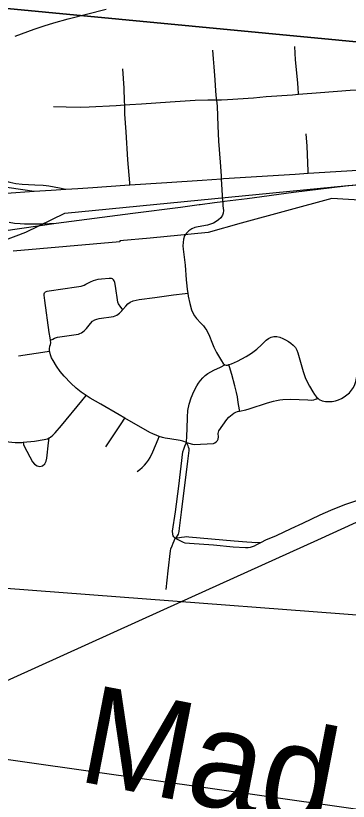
# Model space of a CAD drawing. Extents: x 0 to 34, y 0 to 22.
# Drawn here: x 6.536 to 6.857, y 19.001 to 19.759 of the extents above; entities that cross this region are included whole.
import ezdxf

# ---------------------------------------------------------------- set-up
doc = ezdxf.new("R2010")
doc.units = 0
for name, color, linetype in [('GM_X_City_Street', 7, 'Continuous'), ('GM_X_Corporation', 7, 'Continuous'), ('GM_X_Major_River_Text', 7, 'Continuous'), ('GM_X_Rail_Line', 7, 'Continuous'), ('GM_X_State_Route', 7, 'Continuous'), ('GM_X_Township_Road', 7, 'Continuous'), ('GM_X_US_Route', 7, 'Continuous'), ('SH_Text', 7, 'Continuous')]:
    doc.layers.add(name, color=color, linetype=linetype)

msp = doc.modelspace()

# ---------------------------------------------------------------- linework, layer by layer
at = {"layer": 'GM_X_City_Street'}
for points in [[(6.73606, 19.57997), (6.73629, 19.57584), (6.73663, 19.57115), (6.73642, 19.56869), (6.73581, 19.56661), (6.73418, 19.56425), (6.73206, 19.56219), (6.72964, 19.56044), (6.72706, 19.55899), (6.72429, 19.55791), (6.72138, 19.55714), (6.7122, 19.5555), (6.7091, 19.55468), (6.70611, 19.55343), (6.70338, 19.55166), (6.70105, 19.54935), (6.69928, 19.54657), (6.69817, 19.54348), (6.6977, 19.54026), (6.69769, 19.53705), (6.69791, 19.5339), (6.69967, 19.51846), (6.70082, 19.50417), (6.7013, 19.49845), (6.70171, 19.49486), (6.70224, 19.49145)], [(6.5649, 19.49253), (6.56657, 19.49312), (6.56867, 19.49364), (6.5949, 19.4973), (6.59944, 19.4981), (6.60225, 19.49902), (6.60408, 19.49994), (6.60833, 19.50234), (6.61131, 19.50367), (6.61349, 19.50424), (6.61596, 19.5047), (6.61889, 19.50516), (6.62634, 19.50596), (6.62824, 19.5059), (6.62931, 19.50551)], [(6.63974, 19.47561), (6.63908, 19.4763), (6.63776, 19.47768), (6.63546, 19.48089), (6.63484, 19.48273), (6.63248, 19.49804), (6.63185, 19.50172), (6.63128, 19.50332), (6.6307, 19.5043), (6.62931, 19.50551)], [(6.56982, 19.44585), (6.56961, 19.44807), (6.56846, 19.45347), (6.56427, 19.48416), (6.56364, 19.48927), (6.56375, 19.49081), (6.56416, 19.49168), (6.5649, 19.49253)], [(6.63974, 19.47561), (6.64252, 19.47889), (6.64457, 19.48103), (6.64686, 19.48273), (6.64947, 19.48382), (6.65236, 19.48453), (6.65535, 19.48506), (6.67053, 19.48716), (6.68859, 19.48967), (6.69989, 19.49113), (6.70224, 19.49145)], [(6.70224, 19.49145), (6.70271, 19.48849), (6.70436, 19.48147), (6.70596, 19.47538), (6.70713, 19.47238), (6.70869, 19.46957), (6.71059, 19.46698), (6.71488, 19.46241), (6.71734, 19.45976), (6.71889, 19.45783), (6.7206, 19.45517), (6.72317, 19.44991), (6.72538, 19.44408), (6.72756, 19.43904), (6.73013, 19.43401), (6.73481, 19.42587), (6.73654, 19.42349), (6.73792, 19.42213)], [(6.56982, 19.44585), (6.57201, 19.44699), (6.57368, 19.44784), (6.57643, 19.44876), (6.59674, 19.45175), (6.59823, 19.45221), (6.59972, 19.45303), (6.60242, 19.45493), (6.60453, 19.45733), (6.6083, 19.46215), (6.6104, 19.46413), (6.61275, 19.4657), (6.61441, 19.46625), (6.61676, 19.46672), (6.63062, 19.46876), (6.63237, 19.4693), (6.63374, 19.46995), (6.6363, 19.47195), (6.63852, 19.47419), (6.63974, 19.47561)], [(6.82773, 19.38979), (6.82907, 19.38868), (6.83213, 19.38737), (6.83532, 19.38679), (6.83848, 19.38659), (6.84166, 19.38676), (6.84475, 19.38732), (6.84779, 19.38819), (6.85068, 19.38945), (6.85336, 19.39108), (6.85589, 19.39299), (6.85827, 19.39511), (6.86042, 19.39751), (6.86221, 19.40018), (6.86356, 19.40309), (6.8645, 19.40614), (6.86573, 19.41233), (6.86641, 19.41854), (6.86707, 19.4278), (6.86786, 19.43703), (6.86906, 19.44935), (6.87038, 19.46171), (6.87067, 19.46703)], [(6.74207, 19.42227), (6.74453, 19.42314), (6.75026, 19.42567), (6.75855, 19.43006), (6.76385, 19.43343), (6.76882, 19.43726), (6.77357, 19.44137), (6.7779, 19.44577), (6.78023, 19.44761), (6.78277, 19.44897), (6.78551, 19.44959), (6.78834, 19.44945), (6.79122, 19.4487), (6.79402, 19.44756), (6.79674, 19.44622), (6.79937, 19.44468), (6.80187, 19.44294), (6.80418, 19.44105), (6.80614, 19.43889), (6.80761, 19.43642), (6.80865, 19.43365), (6.81096, 19.42464), (6.81354, 19.41567), (6.81562, 19.40975), (6.81689, 19.40685), (6.81984, 19.40138), (6.82294, 19.39599), (6.82458, 19.39334), (6.82652, 19.39079), (6.82773, 19.38979)], [(6.569, 19.43526), (6.56879, 19.43749), (6.56934, 19.44006), (6.56989, 19.44188), (6.57006, 19.44343), (6.56982, 19.44585)], [(6.5388, 19.43081), (6.56645, 19.43488), (6.569, 19.43526)], [(6.6043, 19.3925), (6.59938, 19.39575), (6.59456, 19.39959), (6.5893, 19.40429), (6.5829, 19.41103), (6.57901, 19.41582), (6.57546, 19.4209), (6.57228, 19.42615), (6.57095, 19.42889), (6.56985, 19.43173), (6.56906, 19.43462), (6.569, 19.43526)], [(6.70098, 19.34699), (6.7015, 19.35347), (6.70167, 19.36018), (6.70194, 19.3716), (6.70252, 19.37793), (6.70372, 19.3842), (6.70556, 19.39031), (6.70803, 19.39618), (6.71106, 19.4018), (6.7128, 19.40448), (6.71473, 19.40704), (6.71684, 19.40947), (6.71918, 19.41171), (6.72172, 19.41371), (6.72446, 19.41543), (6.72731, 19.41689), (6.73382, 19.41986), (6.73792, 19.42213)], [(6.73792, 19.42213), (6.7392, 19.4218), (6.74061, 19.42177), (6.74207, 19.42227)], [(6.7523, 19.37737), (6.75212, 19.37854), (6.75101, 19.38587), (6.75021, 19.39113), (6.74949, 19.39539), (6.74786, 19.40188), (6.74475, 19.41272), (6.74268, 19.42011), (6.74207, 19.42227)], [(6.56842, 19.35155), (6.56969, 19.35221), (6.57223, 19.35425), (6.5744, 19.35656), (6.58045, 19.36363), (6.60015, 19.38748), (6.6043, 19.3925)], [(6.64165, 19.37051), (6.63597, 19.37375), (6.61854, 19.38399), (6.60815, 19.38996), (6.6043, 19.3925)], [(6.7523, 19.37737), (6.75823, 19.37864), (6.76166, 19.37954), (6.77919, 19.38528), (6.7851, 19.38705), (6.78809, 19.38779), (6.79112, 19.38829), (6.79417, 19.3886), (6.80153, 19.38883), (6.81833, 19.38824), (6.82207, 19.38807), (6.82386, 19.38839), (6.82568, 19.38884), (6.82684, 19.38938), (6.82773, 19.38979)], [(6.70098, 19.34699), (6.70672, 19.34538), (6.70833, 19.34515), (6.72709, 19.34607), (6.72836, 19.34667), (6.7298, 19.34772), (6.73089, 19.34886), (6.73169, 19.3504), (6.73189, 19.35269), (6.73174, 19.35567), (6.73184, 19.35721), (6.73244, 19.35845), (6.74009, 19.36939), (6.74178, 19.37148), (6.74342, 19.37297), (6.74501, 19.37416), (6.7467, 19.37531), (6.74854, 19.37626), (6.75033, 19.37695), (6.7523, 19.37737)], [(6.62316, 19.34283), (6.63801, 19.36505), (6.64165, 19.37051)], [(6.67482, 19.35294), (6.67241, 19.3537), (6.66854, 19.35537), (6.66579, 19.35677), (6.64165, 19.37051)], [(6.51602, 19.35276), (6.51749, 19.35181), (6.52034, 19.35036), (6.52331, 19.34921), (6.52636, 19.34833), (6.52946, 19.3477), (6.5326, 19.34731), (6.53574, 19.34711), (6.54203, 19.34723), (6.54343, 19.34737)], [(6.54343, 19.34737), (6.54376, 19.34523), (6.54433, 19.3434), (6.55259, 19.32834), (6.55446, 19.32601), (6.5568, 19.32445), (6.55951, 19.32396), (6.56217, 19.32466), (6.56429, 19.3264), (6.5656, 19.32891), (6.56627, 19.33187), (6.56804, 19.34668), (6.56842, 19.35155)], [(6.54343, 19.34737), (6.55438, 19.34849), (6.56364, 19.34986), (6.56677, 19.35072), (6.56842, 19.35155)], [(6.65348, 19.31914), (6.65593, 19.32102), (6.65826, 19.32304), (6.66045, 19.32524), (6.66246, 19.32759), (6.66426, 19.33009), (6.66589, 19.3327), (6.66862, 19.3382), (6.67375, 19.35039), (6.67482, 19.35294)], [(6.70098, 19.34699), (6.69766, 19.34825), (6.69496, 19.34893), (6.68486, 19.35049), (6.68039, 19.35135), (6.67786, 19.35198), (6.67482, 19.35294)], [(6.69008, 19.25467), (6.68875, 19.25596), (6.68813, 19.25708), (6.68773, 19.25864), (6.6877, 19.26138), (6.69039, 19.28003), (6.69366, 19.30495), (6.69766, 19.33798), (6.69835, 19.34079), (6.69943, 19.34366), (6.70098, 19.34699)], [(6.69008, 19.25467), (6.69157, 19.25577), (6.69249, 19.25697), (6.69329, 19.25846), (6.69404, 19.26122), (6.69448, 19.26425), (6.69629, 19.2797), (6.70247, 19.32909), (6.70373, 19.33941), (6.70368, 19.34096), (6.70316, 19.34263), (6.70259, 19.34394), (6.70098, 19.34699)], [(6.77337, 19.25081), (6.77776, 19.25296), (6.78797, 19.25735), (6.80216, 19.26385), (6.81336, 19.26931), (6.83021, 19.27731), (6.84035, 19.2817), (6.84753, 19.2847), (6.85493, 19.28754), (6.86825, 19.29215)], [(6.68136, 19.20493), (6.68346, 19.22327), (6.68555, 19.2424), (6.68607, 19.24435), (6.68721, 19.24727), (6.68836, 19.24974), (6.68922, 19.25204), (6.69008, 19.25467)], [(6.69008, 19.25467), (6.69622, 19.25577), (6.69915, 19.25611), (6.70093, 19.25623), (6.70345, 19.25611), (6.74722, 19.25195), (6.75939, 19.25104), (6.76403, 19.25067), (6.7676, 19.25057), (6.77337, 19.25081)], [(6.69008, 19.25467), (6.69513, 19.25198), (6.69771, 19.25078), (6.69938, 19.25032), (6.70396, 19.24986), (6.72714, 19.24825), (6.74624, 19.24639), (6.75807, 19.24557), (6.76045, 19.24561), (6.76269, 19.24595), (6.76484, 19.24657), (6.76679, 19.24733), (6.76903, 19.24852), (6.77337, 19.25081)]]:
    msp.add_lwpolyline(points, dxfattribs=at)
at = {"layer": 'GM_X_Corporation'}
for points in [[(6.08229, 20.82057), (7.08216, 20.72429), (6.98964, 19.72208), (5.99165, 19.81795)], [(5.99165, 19.81795), (6.98964, 19.72208), (6.90013, 18.71944), (5.88574, 18.80005)]]:
    msp.add_lwpolyline(points, close=True, dxfattribs=at)
msp.add_lwpolyline([(6.87344, 19.58087), (6.84126, 19.58277), (6.75382, 19.55888), (6.72199, 19.54982), (6.66595, 19.54451), (6.6367, 19.54173), (6.63668, 19.54101), (6.53366, 19.53196)], dxfattribs=at)
at = {"layer": 'GM_X_Rail_Line'}
for points in [[(6.53564, 19.73954), (6.55422, 19.74644), (6.56362, 19.74961), (6.57295, 19.75257), (6.58675, 19.75632), (6.62343, 19.76579)], [(6.49404, 19.53075), (6.54586, 19.55038), (6.58368, 19.56862), (6.85677, 19.5953), (7.4786, 19.63746), (7.52247, 19.64761), (7.56455, 19.65381), (7.67346, 19.65135), (7.70398, 19.6675), (7.78072, 19.69476), (7.84922, 19.71332), (7.8975, 19.72324), (7.94081, 19.72696), (7.9728, 19.72642), (8.01023, 19.72509), (8.06456, 19.71873), (8.1184, 19.70918), (8.15442, 19.70042), (8.43186, 19.60569), (8.84939, 19.56695)], [(6.3823, 19.05105), (6.67911, 19.18588), (6.82772, 19.25299), (7.02632, 19.34372), (7.34943, 19.49118), (7.47336, 19.54747)]]:
    msp.add_lwpolyline(points, dxfattribs=at)
at = {"layer": 'GM_X_State_Route'}
msp.add_line((6.7132, 19.57686), (6.71419, 19.57699), dxfattribs=at)
for points in [[(6.73606, 19.57997), (6.73769, 19.58018), (6.75961, 19.58291), (6.8044, 19.58886), (6.8545, 19.595), (6.87992, 19.59746), (6.8869, 19.59796)], [(6.52738, 19.58798), (6.5542, 19.5897)], [(6.71419, 19.57699), (6.72805, 19.57881), (6.73606, 19.57997)], [(6.57539, 19.55886), (6.64915, 19.56856), (6.69536, 19.57451), (6.7132, 19.57686)], [(6.47278, 19.54455), (6.52439, 19.55146), (6.57539, 19.55886)]]:
    msp.add_lwpolyline(points, dxfattribs=at)
at = {"layer": 'GM_X_Township_Road'}
for points in [[(6.73043, 19.67765), (6.73009, 19.6796), (6.72971, 19.68264), (6.72943, 19.68669), (6.72885, 19.69745), (6.72778, 19.70981), (6.72726, 19.71777), (6.72663, 19.72609)], [(6.80905, 19.68313), (6.80901, 19.68451), (6.80884, 19.68896), (6.80851, 19.69457), (6.80636, 19.71684), (6.80586, 19.72314), (6.80551, 19.72947)], [(6.64142, 19.67288), (6.64131, 19.67678), (6.6408, 19.68928), (6.63977, 19.70795)], [(6.88463, 19.68815), (6.88123, 19.68815), (6.87636, 19.68815), (6.85898, 19.68697), (6.83045, 19.68472), (6.80905, 19.68313)], [(6.73043, 19.67765), (6.7216, 19.67766), (6.70955, 19.67739), (6.68545, 19.67595), (6.65773, 19.67405), (6.64647, 19.67321), (6.64142, 19.67288)], [(6.80905, 19.68313), (6.80348, 19.68272), (6.77811, 19.68084), (6.76577, 19.6798), (6.74058, 19.67792), (6.7349, 19.6777), (6.73043, 19.67765)], [(6.73486, 19.60184), (6.7347, 19.60474), (6.73373, 19.61771), (6.73243, 19.63814), (6.73157, 19.65311), (6.73091, 19.67203), (6.73075, 19.67479), (6.73043, 19.67765)], [(6.64142, 19.67288), (6.63318, 19.67236), (6.60701, 19.67093), (6.59867, 19.67077), (6.58492, 19.671), (6.57258, 19.67124)], [(6.64639, 19.59598), (6.64624, 19.59792), (6.6446, 19.62026), (6.6427, 19.64721), (6.64165, 19.66427), (6.64142, 19.67288)], [(6.81851, 19.60714), (6.81843, 19.60909), (6.81753, 19.63317), (6.81669, 19.64522)], [(6.4813, 19.61594), (6.48374, 19.61744), (6.48555, 19.61807), (6.48727, 19.61794), (6.48929, 19.61724), (6.49134, 19.6161), (6.50198, 19.60993), (6.51022, 19.60575), (6.5187, 19.60209), (6.52451, 19.60006), (6.53044, 19.59846), (6.53647, 19.59728), (6.54257, 19.59659), (6.54863, 19.59625), (6.55484, 19.59605), (6.5627, 19.59574), (6.56576, 19.59545), (6.56806, 19.5951), (6.57848, 19.59301), (6.58447, 19.59182)], [(6.73606, 19.57997), (6.73545, 19.59118), (6.73486, 19.60184)]]:
    msp.add_lwpolyline(points, dxfattribs=at)
at = {"layer": 'GM_X_US_Route'}
msp.add_line((6.7132, 19.57686), (6.71419, 19.57699), dxfattribs=at)
for points in [[(6.42199, 19.65024), (6.42978, 19.64661), (6.43648, 19.64313), (6.44301, 19.63898), (6.46048, 19.6283), (6.47585, 19.61916), (6.4813, 19.61594), (6.49344, 19.60875), (6.50452, 19.60279), (6.51301, 19.59868), (6.51885, 19.59632), (6.52486, 19.59445), (6.53005, 19.59326), (6.5542, 19.5897)], [(6.59614, 19.59258), (6.61074, 19.59354), (6.64172, 19.59567), (6.64639, 19.59598), (6.68197, 19.59835), (6.71604, 19.60056), (6.73486, 19.60184), (6.73673, 19.60196), (6.80582, 19.60634), (6.81851, 19.60714), (6.86639, 19.61017), (6.88596, 19.61144), (6.91107, 19.61319), (6.94507, 19.61542), (6.96421, 19.61647), (6.98238, 19.61746), (6.98882, 19.61794), (7.00114, 19.61886), (7.0033, 19.61902), (7.01383, 19.6198), (7.06589, 19.62362), (7.19111, 19.6319), (7.22109, 19.63387)], [(6.73606, 19.57997), (6.73769, 19.58018), (6.75961, 19.58291), (6.8044, 19.58886), (6.8545, 19.595), (6.87992, 19.59746), (6.8869, 19.59796)], [(6.5542, 19.5897), (6.57046, 19.59091), (6.58447, 19.59182), (6.59614, 19.59258)], [(6.71419, 19.57699), (6.72805, 19.57881), (6.73606, 19.57997)], [(6.57539, 19.55886), (6.64915, 19.56856), (6.69536, 19.57451), (6.7132, 19.57686)], [(6.52992, 19.55991), (6.53505, 19.55901), (6.54052, 19.55847), (6.54478, 19.55821), (6.54957, 19.55827), (6.5622, 19.55836), (6.57539, 19.55886)]]:
    msp.add_lwpolyline(points, dxfattribs=at)
at = {"layer": 'SH_Text'}
msp.add_lwpolyline([(9.47688, 18.98166), (4.03377, 19.39562), (9.47688, 18.6217)], close=True, dxfattribs=at)

# ---------------------------------------------------------------- texts
at = {"layer": 'GM_X_Major_River_Text'}
msp.add_text('Mad', height=0.094693, rotation=349.00863, dxfattribs=at).set_placement((6.59427, 19.0205))

doc.saveas('drawing.dxf')
